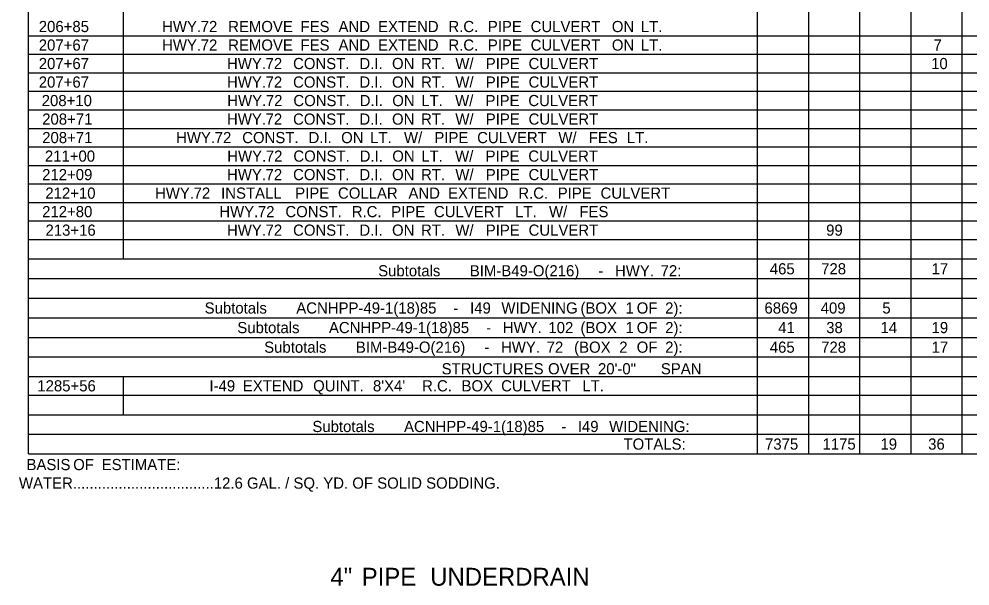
# Model space of a CAD drawing. Extents: x 1226561 to 1228164, y 151309 to 152305.
# Drawn here: x 1226561 to 1226933.4, y 151822.8 to 152044.7 of the extents above; entities that cross this region are included whole.
import ezdxf

# ---------------------------------------------------------------- set-up
doc = ezdxf.new("R2010")
doc.units = 0
doc.layers.add('R_Dimension', color=7, linetype='Continuous')

msp = doc.modelspace()

# ---------------------------------------------------------------- linework, layer by layer
at = {"layer": 'R_Dimension'}
for p, q in [((1226564.67, 151874.5), (1226564.67, 152265.3)), ((1226601.93, 151950.78), (1226601.93, 152265.3)), ((1226850.27, 151874.5), (1226850.27, 152265.3)), ((1226870.3, 151874.5), (1226870.3, 152219.27)), ((1226890.33, 151874.5), (1226890.33, 152219.27)), ((1226910.36, 151874.5), (1226910.36, 152219.27)), ((1226930.39, 151874.5), (1226930.39, 152219.27)), ((1226564.67, 152038.15), (1228152.39, 152038.15)), ((1226564.67, 152030.9), (1228152.39, 152030.9)), ((1226564.67, 152023.66), (1228152.39, 152023.66)), ((1226564.67, 152016.41), (1228152.39, 152016.41)), ((1226564.67, 152009.17), (1228152.39, 152009.17)), ((1226564.67, 152001.92), (1228152.39, 152001.92)), ((1226564.67, 151994.68), (1228152.39, 151994.68)), ((1226564.67, 151987.43), (1228152.39, 151987.43)), ((1226564.67, 151980.19), (1228152.39, 151980.19)), ((1226564.67, 151972.94), (1228152.39, 151972.94)), ((1226564.67, 151965.7), (1228152.39, 151965.7)), ((1226564.67, 151958.45), (1228152.39, 151958.45)), ((1226564.67, 151950.78), (1228152.39, 151950.78)), ((1226564.67, 151943.11), (1228152.39, 151943.11)), ((1226564.67, 151935.44), (1228152.39, 151935.44)), ((1226850.27, 151912.43), (1226850.27, 151935.44)), ((1226870.3, 151912.43), (1226870.3, 151935.44)), ((1226890.33, 151912.43), (1226890.33, 151935.44)), ((1226910.36, 151912.43), (1226910.36, 151935.44)), ((1226930.39, 151912.43), (1226930.39, 151935.44)), ((1226564.67, 151927.77), (1228152.39, 151927.77)), ((1226564.67, 151920.1), (1228152.39, 151920.1)), ((1226564.67, 151912.43), (1228152.39, 151912.43)), ((1226564.67, 151904.75), (1228152.39, 151904.75)), ((1226601.93, 151889.84), (1226601.93, 151904.75)), ((1226850.27, 151874.5), (1226850.27, 151904.75)), ((1226870.3, 151874.5), (1226870.3, 151904.75)), ((1226890.33, 151874.5), (1226890.33, 151904.75)), ((1226910.36, 151874.5), (1226910.36, 151904.75)), ((1226930.39, 151874.5), (1226930.39, 151904.75)), ((1226564.67, 151897.51), (1228152.39, 151897.51)), ((1226564.67, 151889.84), (1228152.39, 151889.84)), ((1226564.67, 151882.17), (1228152.39, 151882.17)), ((1226564.67, 151874.5), (1228152.39, 151874.5))]:
    msp.add_line(p, q, dxfattribs=at)

# ---------------------------------------------------------------- texts
for s, height, p in [('206+85', 4.371, (1226568.7, 152039.59)), ('HWY.', 4.371, (1226617, 152039.59)), (' 72', 4.371, (1226630.49, 152039.59)), (' REMOVE', 4.371, (1226641.27, 152039.59)), (' FES', 4.371, (1226669.59, 152039.59)), (' AND', 4.371, (1226684.49, 152039.59)), (' EXTEND', 4.371, (1226699.98, 152039.59)), (' R.C.', 4.371, (1226727.52, 152039.59)), (' PIPE', 4.371, (1226742.97, 152039.59)), (' CULVERT', 4.371, (1226759.73, 152039.59)), (' ON', 4.371, (1226791.53, 152039.59)), (' LT.', 4.371, (1226802.89, 152039.59)), ('207+67', 4.371, (1226568.7, 152032.34)), ('HWY.', 4.371, (1226617, 152032.34)), (' 72', 4.371, (1226630.49, 152032.34)), (' REMOVE', 4.371, (1226641.27, 152032.34)), (' FES', 4.371, (1226669.59, 152032.34)), (' AND', 4.371, (1226684.49, 152032.34)), (' EXTEND', 4.371, (1226699.98, 152032.34)), (' R.C.', 4.371, (1226727.52, 152032.34)), (' PIPE', 4.371, (1226742.97, 152032.34)), (' CULVERT', 4.371, (1226759.73, 152032.34)), (' ON', 4.371, (1226791.53, 152032.34)), (' LT.', 4.371, (1226802.89, 152032.34)), ('7', 4.37, (1226919.14, 152032.34)), ('207+67', 4.371, (1226568.7, 152025.1)), ('HWY.', 4.371, (1226642.42, 152025.1)), (' 72', 4.371, (1226655.91, 152025.1)), (' CONST.', 4.371, (1226666.68, 152025.1)), (' D.I.', 4.371, (1226692.67, 152025.1)), (' ON', 4.371, (1226705.44, 152025.1)), (' RT.', 4.371, (1226716.8, 152025.1)), (' W/', 4.371, (1226730.25, 152025.1)), (' PIPE', 4.371, (1226742.16, 152025.1)), (' CULVERT', 4.371, (1226758.92, 152025.1)), ('10', 4.371, (1226918.23, 152025.1)), ('207+67', 4.371, (1226568.7, 152017.85)), ('HWY.', 4.371, (1226642.42, 152017.85)), (' 72', 4.371, (1226655.91, 152017.85)), (' CONST.', 4.371, (1226666.68, 152017.85)), (' D.I.', 4.371, (1226692.67, 152017.85)), (' ON', 4.371, (1226705.44, 152017.85)), (' RT.', 4.371, (1226716.8, 152017.85)), (' W/', 4.371, (1226730.25, 152017.85)), (' PIPE', 4.371, (1226742.16, 152017.85)), (' CULVERT', 4.371, (1226758.92, 152017.85)), ('208+10', 4.371, (1226569.85, 152010.61)), ('HWY.', 4.371, (1226642.52, 152010.61)), (' 72', 4.371, (1226656.01, 152010.61)), (' CONST.', 4.371, (1226666.79, 152010.61)), (' D.I.', 4.371, (1226692.77, 152010.61)), (' ON', 4.371, (1226705.54, 152010.61)), (' LT.', 4.371, (1226716.9, 152010.61)), (' W/', 4.371, (1226730.15, 152010.61)), (' PIPE', 4.371, (1226742.06, 152010.61)), (' CULVERT', 4.371, (1226758.82, 152010.61)), ('208+71', 4.371, (1226570.04, 152003.36)), ('HWY.', 4.371, (1226642.42, 152003.36)), (' 72', 4.371, (1226655.91, 152003.36)), (' CONST.', 4.371, (1226666.68, 152003.36)), (' D.I.', 4.371, (1226692.67, 152003.36)), (' ON', 4.371, (1226705.44, 152003.36)), (' RT.', 4.371, (1226716.8, 152003.36)), (' W/', 4.371, (1226730.25, 152003.36)), (' PIPE', 4.371, (1226742.16, 152003.36)), (' CULVERT', 4.371, (1226758.92, 152003.36)), ('208+71', 4.371, (1226570.04, 151996.12)), ('HWY.', 4.371, (1226622.49, 151996.12)), (' 72', 4.371, (1226635.98, 151996.12)), (' CONST.', 4.371, (1226646.76, 151996.12)), (' D.I.', 4.371, (1226672.74, 151996.12)), (' ON', 4.371, (1226685.51, 151996.12)), (' LT.', 4.371, (1226696.87, 151996.12)), (' W/', 4.371, (1226710.12, 151996.12)), (' PIPE', 4.371, (1226722.03, 151996.12)), (' CULVERT', 4.371, (1226738.79, 151996.12)), (' W/', 4.371, (1226770.59, 151996.12)), (' FES', 4.371, (1226782.5, 151996.12)), (' LT.', 4.371, (1226797.4, 151996.12)), ('211+00', 4.371, (1226571.09, 151988.87)), ('HWY.', 4.371, (1226642.52, 151988.87)), (' 72', 4.371, (1226656.01, 151988.87)), (' CONST.', 4.371, (1226666.79, 151988.87)), (' D.I.', 4.371, (1226692.77, 151988.87)), (' ON', 4.371, (1226705.54, 151988.87)), (' LT.', 4.371, (1226716.9, 151988.87)), (' W/', 4.371, (1226730.15, 151988.87)), (' PIPE', 4.371, (1226742.06, 151988.87)), (' CULVERT', 4.371, (1226758.82, 151988.87)), ('212+09', 4.371, (1226570.02, 151981.63)), (' 72', 4.371, (1226655.91, 151981.63)), (' CONST.', 4.371, (1226666.68, 151981.63)), (' ON', 4.371, (1226705.44, 151981.63)), (' W/', 4.371, (1226730.25, 151981.63)), (' CULVERT', 4.371, (1226758.92, 151981.63)), ('HWY.', 4.371, (1226642.42, 151981.63)), (' D.I.', 4.371, (1226692.67, 151981.63)), (' RT.', 4.371, (1226716.8, 151981.63)), (' PIPE', 4.371, (1226742.16, 151981.63)), ('212+10', 4.371, (1226571.26, 151974.38)), ('HWY.', 4.371, (1226614.23, 151974.38)), (' 72', 4.371, (1226627.72, 151974.38)), (' INSTALL', 4.371, (1226638.49, 151974.38)), (' PIPE', 4.371, (1226667.51, 151974.38)), (' COLLAR', 4.371, (1226684.27, 151974.38)), (' AND', 4.371, (1226711.87, 151974.38)), (' EXTEND', 4.371, (1226727.36, 151974.38)), (' R.C.', 4.371, (1226754.9, 151974.38)), (' PIPE', 4.371, (1226770.35, 151974.38)), (' CULVERT', 4.371, (1226787.11, 151974.38)), ('212+80', 4.371, (1226570.02, 151967.14)), ('HWY.', 4.371, (1226639.41, 151967.14)), (' 72', 4.371, (1226652.9, 151967.14)), (' CONST.', 4.371, (1226663.67, 151967.14)), (' R.C.', 4.371, (1226689.66, 151967.14)), (' PIPE', 4.371, (1226705.11, 151967.14)), (' CULVERT', 4.371, (1226721.87, 151967.14)), (' LT.', 4.371, (1226753.67, 151967.14)), (' W/', 4.371, (1226766.92, 151967.14)), (' FES', 4.371, (1226778.83, 151967.14)), ('213+16', 4.371, (1226571.33, 151959.89)), ('HWY.', 4.371, (1226642.42, 151959.89)), (' 72', 4.371, (1226655.91, 151959.89)), (' CONST.', 4.371, (1226666.68, 151959.89)), (' D.I.', 4.371, (1226692.67, 151959.89)), (' ON', 4.371, (1226705.44, 151959.89)), (' RT.', 4.371, (1226716.8, 151959.89)), (' W/', 4.371, (1226730.25, 151959.89)), (' PIPE', 4.371, (1226742.16, 151959.89)), (' CULVERT', 4.371, (1226758.92, 151959.89)), ('99', 4.371, (1226877.1, 151959.89)), ('465', 4.371, (1226855.02, 151944.76)), ('728', 4.371, (1226875.15, 151944.76)), ('17', 4.371, (1226918.42, 151944.76)), ('Subtotals', 4.371, (1226701.63, 151943.99)), (' BIM-B49-O(216)', 4.3711, (1226735.91, 151943.99)), (' -', 4.371, (1226786.27, 151943.99)), (' HWY.', 4.371, (1226792.77, 151943.99)), (' 72:', 4.371, (1226810.64, 151943.99)), ('Subtotals', 4.371, (1226633.66, 151929.42)), (' ACNHPP-49-1(18)85', 4.3711, (1226667.94, 151929.42)), (' (BOX', 4.371, (1226779.25, 151929.42)), (' 2):', 4.371, (1226812.43, 151929.42)), (' -', 4.371, (1226729.51, 151929.42)), (' I49', 4.371, (1226736.02, 151929.42)), (' WIDENING', 4.371, (1226748.27, 151929.42)), (' 1', 4.371, (1226796.9, 151929.42)), (' OF', 4.371, (1226801.27, 151929.42)), ('6869', 4.371, (1226852.94, 151929.42)), ('409', 4.371, (1226874.96, 151929.42)), ('5', 4.37, (1226899.11, 151929.42)), ('Subtotals', 4.371, (1226646.46, 151921.75)), (' ACNHPP-49-1(18)85', 4.3711, (1226680.74, 151921.75)), (' -', 4.371, (1226742.32, 151921.75)), (' HWY.', 4.371, (1226748.82, 151921.75)), (' 102', 4.371, (1226766.68, 151921.75)), (' (BOX', 4.371, (1226779.25, 151921.75)), (' 1', 4.371, (1226796.9, 151921.75)), (' OF', 4.371, (1226801.27, 151921.75)), (' 2):', 4.371, (1226812.43, 151921.75)), ('41', 4.371, (1226858.32, 151921.75)), ('38', 4.371, (1226877.12, 151921.75)), ('14', 4.371, (1226898.39, 151921.75)), ('19', 4.371, (1226918.4, 151921.75)), ('Subtotals', 4.371, (1226656.99, 151914.08)), (' BIM-B49-O(216)', 4.3711, (1226691.27, 151914.08)), (' -', 4.371, (1226741.63, 151914.08)), (' HWY.', 4.371, (1226748.13, 151914.08)), (' 72', 4.371, (1226766, 151914.08)), (' (BOX', 4.371, (1226776.77, 151914.08)), (' 2', 4.371, (1226794.43, 151914.08)), (' OF', 4.371, (1226801.27, 151914.08)), (' 2):', 4.371, (1226812.43, 151914.08)), ('465', 4.371, (1226855.02, 151914.08)), ('728', 4.371, (1226875.15, 151914.08)), ('17', 4.371, (1226918.42, 151914.08)), ('STRUCTURES', 4.371, (1226726.49, 151905.63)), (' OVER', 4.371, (1226766.55, 151905.63)), (' 20\'-0"', 4.371, (1226786.1, 151905.63)), (' SPAN', 4.371, (1226810.74, 151905.63)), ('1285+56', 4.371, (1226568.13, 151898.95)), ('I-49', 4.371, (1226635.54, 151898.95)), (' EXTEND', 4.371, (1226647, 151898.95)), (' QUINT.', 4.371, (1226674.53, 151898.95)), (" 8'X4'", 4.371, (1226697.97, 151898.95)), (' R.C.', 4.371, (1226717.21, 151898.95)), (' BOX', 4.371, (1226732.66, 151898.95)), (' CULVERT', 4.371, (1226748.18, 151898.95)), (' LT.', 4.371, (1226779.99, 151898.95)), ('Subtotals', 4.371, (1226675.86, 151883.04)), (' ACNHPP-49-1(18)85', 4.3711, (1226710.14, 151883.04)), (' I49', 4.371, (1226778.21, 151883.04)), (' WIDENING:', 4.371, (1226790.47, 151883.04)), (' -', 4.371, (1226771.71, 151883.04)), ('TOTALS:', 4.371, (1226797.73, 151876.15)), ('7375', 4.371, (1226853.16, 151876.15)), ('1175', 4.371, (1226875.67, 151876.15)), ('19', 4.371, (1226898.37, 151876.15)), ('36', 4.371, (1226917.06, 151876.15)), ('BASIS', 4.371, (1226563.9, 151868.13)), (' OF', 4.371, (1226580.56, 151868.13)), (' ESTIMATE:', 4.371, (1226591.71, 151868.13)), (' WATER..................................12.6 GAL. / SQ. YD. OF SOLID SODDING.', 4.3711, (1226559.31, 151860.88)), ('4"', 7, (1226682.95, 151822.89)), (' PIPE', 7, (1226692.6, 151822.89)), (' UNDERDRAIN', 7, (1226719.44, 151822.89))]:
    msp.add_text(s, height=height, dxfattribs=at).set_placement(p)

doc.saveas('drawing.dxf')
